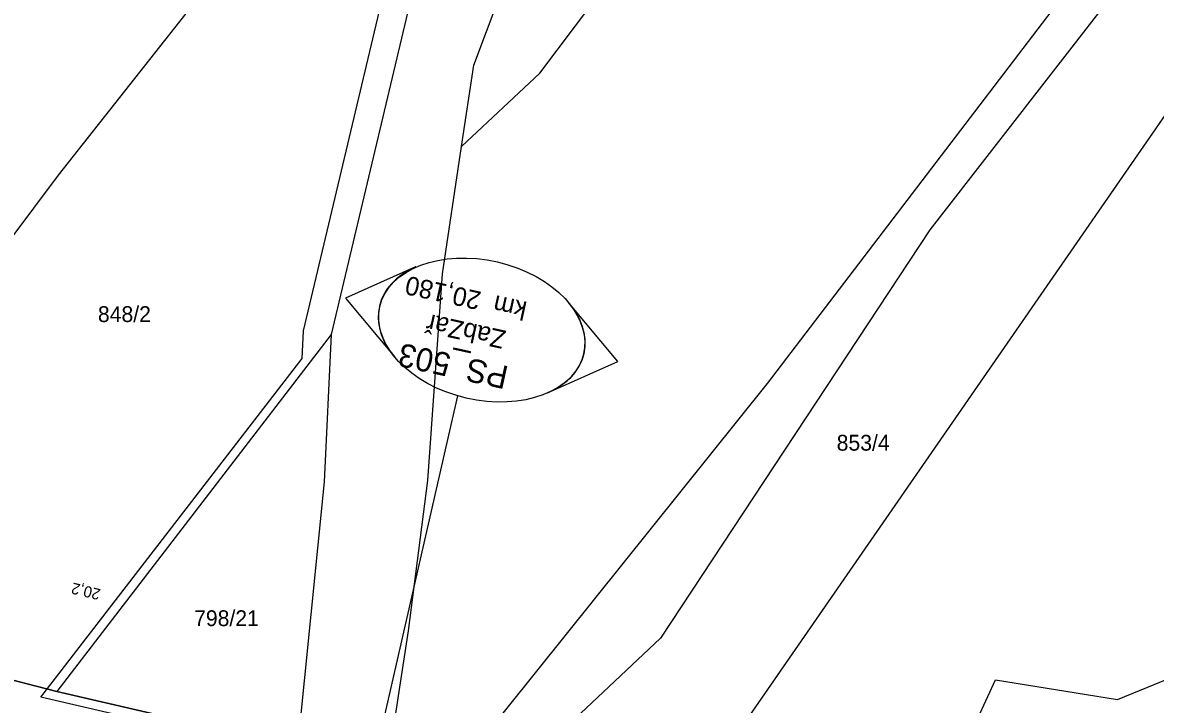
# Model space of a CAD drawing. Extents: x -7483133 to -743169, y -11317770 to -1127091.
# Drawn here: x -747630 to -747508.3, y -1131690.5 to -1131617.3 of the extents above; entities that cross this region are included whole.
import ezdxf

# ---------------------------------------------------------------- set-up
doc = ezdxf.new("R2010")
doc.units = 0
for name, color, linetype in [('_Násyp', 7, 'Continuous'), ('_TRASA_vedení kabelu_CEZ', 7, 'Continuous'), ('bublina_fialová_čára_tenká', 7, 'Continuous'), ('bublina_růžová_230_čára_tučná', 7, 'Continuous'), ('C3D-TRASA-HEKTOM', 7, 'Continuous'), ('Hranice parcel', 7, 'Continuous'), ('Parcelní čísla', 7, 'Continuous'), ('Vrstva 53', 7, 'Continuous')]:
    doc.layers.add(name, color=color, linetype=linetype)

msp = doc.modelspace()

# ---------------------------------------------------------------- linework, layer by layer
at = {"layer": '_TRASA_vedení kabelu_CEZ'}
msp.add_lwpolyline([(-747606.66, -1131708.94), (-747603.52, -1131695.37), (-747628.04, -1131689.7), (-747599.97, -1131653.35), (-747599.82, -1131650.35), (-747590.15, -1131609.62)], dxfattribs=at)
at = {"layer": 'bublina_fialová_čára_tenká'}
msp.add_line((-747593.83, -1131703.74), (-747583.24, -1131657.36), dxfattribs=at)
at = {"layer": 'bublina_růžová_230_čára_tučná'}
for p, q in [((-747587.77, -1131643.5), (-747595.31, -1131646.86)), ((-747587.77, -1131643.5), (-747595.31, -1131646.86)), ((-747595.31, -1131646.86), (-747590.02, -1131653.2)), ((-747595.31, -1131646.86), (-747590.02, -1131653.2)), ((-747566.05, -1131653.67), (-747571.34, -1131647.34)), ((-747566.05, -1131653.67), (-747571.34, -1131647.34)), ((-747573.59, -1131657.03), (-747566.05, -1131653.67)), ((-747573.59, -1131657.03), (-747566.05, -1131653.67))]:
    msp.add_line(p, q, dxfattribs=at)
msp.add_ellipse((-747580.66, -1131650.28), major_axis=(-10.96, 2.54), ratio=0.666667, dxfattribs=at)
for centre, major_axis in [((-747580.69, -1131650.25), (-10.96, 2.54)), ((-747580.66, -1131650.28), (10.96, -2.54))]:
    msp.add_ellipse(centre, major_axis=major_axis, ratio=0.666473, start_param=5.557317, end_param=7.009053, dxfattribs=at)
at = {"layer": 'Hranice parcel'}
for p, q in [((-747596.84, -1131650.77), (-747626.3, -1131689.08)), ((-747626.3, -1131689.08), (-747660.92, -1131680.14)), ((-747600.45, -1131695.05), (-747626.3, -1131689.08))]:
    msp.add_line(p, q, dxfattribs=at)
for points in [[(-747443.45, -1131514.26), (-747480.55, -1131563.87), (-747518.42, -1131614.59), (-747550, -1131656.02), (-747584.22, -1131698.64)], [(-747582.84, -1131630.56), (-747581.53, -1131621.85), (-747565.63, -1131579.59), (-747560.43, -1131550.33)], [(-747660.92, -1131680.14), (-747626.14, -1131633.64), (-747573.17, -1131566.58)], [(-747573.17, -1131566.58), (-747574.95, -1131575.62), (-747587.27, -1131610.47), (-747596.84, -1131650.77)], [(-747582.84, -1131630.56), (-747574.44, -1131622.7), (-747534.47, -1131569.66)], [(-747512.18, -1131613.29), (-747532.53, -1131639.52), (-747561.47, -1131683.37), (-747579.28, -1131700.12)], [(-747512.18, -1131613.29), (-747502.43, -1131618.94), (-747504.69, -1131623.44), (-747559.41, -1131702.48)], [(-747590.72, -1131696.79), (-747588.52, -1131682.57), (-747586.46, -1131666.42), (-747584.9, -1131644.26), (-747582.84, -1131630.56)], [(-747596.84, -1131650.77), (-747597.6, -1131666.57), (-747600.45, -1131695.05)], [(-747528.4, -1131694.14), (-747525.49, -1131687.82), (-747512.4, -1131689.95), (-747488.58, -1131680.22)]]:
    msp.add_lwpolyline(points, dxfattribs=at)
at = {"layer": 'Vrstva 53'}
msp.add_lwpolyline([(-747953.56, -1131610.11), (-747915.42, -1131619.45), (-747897.61, -1131623.76), (-747844.03, -1131636.81), (-747806.67, -1131645.86), (-747772.35, -1131654.05), (-747751.97, -1131658.69), (-747733.77, -1131662.83), (-747698.69, -1131671.28), (-747680.04, -1131675.66), (-747660.92, -1131680.14), (-747626.3, -1131689.08), (-747600.45, -1131695.05), (-747601.8, -1131707.17)], dxfattribs=at)

# ---------------------------------------------------------------- texts
at = {"layer": '_Násyp'}
for s, height, p in [('km  20,180', 2, (-747575.69, -1131647.28)), ('ZabZař', 2, (-747577.96, -1131650.38)), ('PS_503', 2.5, (-747577.66, -1131654.21))]:
    msp.add_text(s, height=height, rotation=167.6146, dxfattribs=at).set_placement(p)
at = {"layer": 'C3D-TRASA-HEKTOM'}
msp.add_text('20,2', height=1.2, rotation=166.3961, dxfattribs=at).set_placement((-747621.53, -1131678.12))
at = {"layer": 'Parcelní čísla'}
for s, p in [('848/2', (-747621.89, -1131649.42)), ('853/4', (-747542.55, -1131663.23)), ('798/21', (-747611.56, -1131682.07))]:
    msp.add_text(s, height=1.7, dxfattribs=at).set_placement(p)

doc.saveas('drawing.dxf')
